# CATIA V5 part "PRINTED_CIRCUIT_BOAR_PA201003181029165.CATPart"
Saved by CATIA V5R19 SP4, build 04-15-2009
Part number: PRINTED_CIRCUIT_BOAR_PA201003181029165
Bounding box of the stored display mesh (mm): x -15 to 15, y -2.5 to 2.5, z -1 to 0
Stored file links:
  E:\CadInnWork\InWork\PRINTED_CIRCUIT_BOAR_PA201003181029165.CATPart
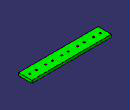
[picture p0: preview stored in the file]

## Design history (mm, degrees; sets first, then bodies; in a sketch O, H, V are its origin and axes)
Parameters
  Update = false
  PDM_version = "A"
  PDM_iteration = 1
  PDM_owner = "moren                    "
  PDM_comment = ""
  PDM_partnumber = "PA002170EA6A57201003181029160005"
Body1 (main body)
  Sketch1 on xy-plane, origin (0, 0, 0), H (1, 0, 0), V (0, 1, 0)
    line L1 (15, 2.5) -> (15, -2.5)
    line L2 (15, -2.5) -> (0, -2.5)
    line L3 (0, -2.5) -> (0, 2.5)
    line L4 (0, 2.5) -> (15, 2.5)
    reference intersected line E1 through (0, 0) direction (0, 1) from yz-plane
    length L4 = 15
    distance L2 L4 = 5
    vertical: L1 V, L3 V
    horizontal: L2 H, L4 H
    equidistance: L2 L4 O
    coincidence: L3 E1
  Pad1: profile Sketch1, direction (0, 0, -1), length 1
  Sketch2 on start face of Pad1, origin (0, 0, 0), H (1, 0, 0), V (0, 1, 0)
    line L1 (1.52, 0.25) -> (1.02, 0.25)
    line L2 (1.02, 0.25) -> (1.02, -0.25)
    line L3 (1.02, -0.25) -> (1.52, -0.25)
    line L4 (1.52, -0.25) -> (1.52, 0.25)
    reference intersected line E1 through (0, 0) direction (-1, 0) from zx-plane
    construction line L5 (1.27, 4.773) -> (1.27, -6.8318)
    reference intersected line E2 through (0, 0) direction (0, 1) from yz-plane
    distance L5 E2 = 1.27
    length L3 = 0.5
    length L2 = 0.5
    horizontal: L1 H, L3 H
    vertical: L2 V, L4 V, L5 V
    symmetry: L3 L1 E1, L2 L4 L5
  Pocket1: profile Sketch2, direction (0, 0, -1), through (limit type 3)
  Plane1: type Offset, RefPlane yz-plane, Offset 6
  Sketch3 on start face of Pad1, origin (0, 0, 0), H (1, 0, 0), V (0, 1, 0)
    line L1 (4.98, 0.25) -> (4.48, 0.25)
    line L2 (4.48, 0.25) -> (4.48, -0.25)
    line L3 (4.48, -0.25) -> (4.98, -0.25)
    line L4 (4.98, -0.25) -> (4.98, 0.25)
    construction line L5 (4.73, 1.2678) -> (4.73, -1.7139)
    reference intersected line E1 through (6, 0) direction (0, 1) from Plane1
    reference intersected line E2 through (0, 0) direction (-1, 0) from zx-plane
    distance E1 L5 = 1.27
    distance L4 L2 = 0.5
    length L2 = 0.5
    horizontal: L1 H, L3 H
    vertical: L2 V, L4 V, L5 V
    symmetry: L2 L4 L5, L3 L1 E2
  Pocket2: profile Sketch3, direction (0, 0, -1), through (limit type 3)
  Mirror1: of Pocket2, about Plane1
  RectPattern1: of Pocket2, direction 1 instances 2, spacing 6, along edge [face of Pad1 from Sketch1.L2 | start face of Pad1]
  Plane2: type Offset, RefPlane Plane1, Offset 6
  Sketch4 on start face of Pad1, origin (0, 0, 0), H (1, 0, 0), V (0, 1, 0)
    line L1 (13.02, 0.25) -> (13.52, 0.25)
    line L2 (13.52, 0.25) -> (13.52, -0.25)
    line L3 (13.52, -0.25) -> (13.02, -0.25)
    line L4 (13.02, -0.25) -> (13.02, 0.25)
    reference projected line E1 (10.98, -0.25) -> (10.98, 0.25) from edge [start face of Pad1 | face of RectPattern1]
    reference intersected line E2 through (12, 0) direction (0, 1) from Plane2
    reference intersected line E3 through (0, 0) direction (-1, 0) from zx-plane
    length L3 = 0.5
    length L2 = 0.5
    horizontal: L1 H, L3 H
    vertical: L2 V, L4 V
    symmetry: L4 E1 E2, L3 L1 E3
  Pocket3: profile Sketch4, direction (0, 0, -1), through (limit type 3)
  Mirror2: of the body so far, about yz-plane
